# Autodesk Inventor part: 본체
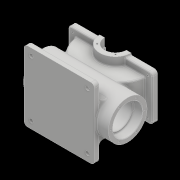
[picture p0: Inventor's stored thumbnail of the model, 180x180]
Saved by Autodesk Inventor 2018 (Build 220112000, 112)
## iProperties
Created: 2023-07
Part Number: 본체
Material: 일반
Document SubType Name: Modeling
Designer: home
Density: 1 g/cm^3
Appearance: 기본값
Author: home
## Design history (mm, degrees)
sketch "스케치1"
  geometry: L1 (-100, -100)-(100, -100); L2 (100, -100)-(100, 100); L3 (100, 100)-(-100, 100); L4 (-100, 100)-(-100, -100); L5 (-100, -100)-(100, 100); L6 (100, -100)-(-100, 100); 1 further point
  constraints: 12 end point, 2 midpoint, 2 parallel, 1 horizontal, 1 perpendicular
  dimensions: "d0" = 200 distance of L3.end L2.end; "d1" = 200 distance of L2.end L1.end
extrude "돌출1" new body sketch "스케치1" distance "d2" = 15; taper "d3" = 0 deg
sketch "스케치3"
  geometry: C1 r 55 at (60, 0); 1 further point
  constraints: 1 centre point, 1 horizontal alignment
  dimensions: "d10" = 110 diameter of C1; "d11" = 60 distance of point (0, 0) C1.centre
extrude "돌출3" join sketch "스케치3" distance "d12" = 135; taper "d14" = 0 deg; dims "d13" = 107, "d15" = 0
sketch "스케치4"
  geometry: L1 (-100, 160)-(100, 160); A1 r 100 centre (0, 160) between (-100, 160) and (100, 160); 1 further point
  constraints: 2 end point, 2 point on circle, 1 centre point, 1 horizontal, 1 vertical alignment
  dimensions: "d16" = 200 diameter of A1; "d17" = 160 distance of point (0, 0) A1.centre; "d18" = 160 distance from line of point (0, 0) L1
extrude "돌출4" join sketch "스케치4" distance "d19" = 45; taper "d21" = 0 deg; dims "d20" = 45, "d22" = 0
sketch "스케치5"
  geometry: L1 (-20, 110)-(220, 110); L2 (220, 110)-(220, -20); L3 (220, -20)-(-20, -20); L4 (-20, -20)-(-20, 110); L5 (-20, 110)-(220, -20); L6 (220, 110)-(-20, -20); 1 further point
  constraints: 12 end point, 2 midpoint, 2 parallel, 1 horizontal, 1 perpendicular
  dimensions: "d23" = 240 distance of L2.end L3.end; "d24" = 130 distance of L1.end L2.end
extrude "돌출5" join sketch "스케치5" distance "d25" = 15; taper "d26" = 0 deg
sketch "스케치7"
  geometry: L1 (-120, 160)-(120, 160) reference; L2 (-45, 160)-(45, 160); A1 r 45 centre (0, 160) between (-45, 160) and (45, 160); 1 further point
  constraints: 2 end point, 2 point on circle, 2 point on line, 1 centre point, 1 midpoint
  dimensions: "d32" = 90 diameter of A1
extrude "돌출7" join sketch "스케치7" distance "d33" = 70; taper "d35" = 0 deg; dims "d34" = 70, "d36" = 0
sketch "스케치8"
  geometry: L1 (-45, 160)-(45, 160) reference; C1 r 87 at (0, 160); 1 further point
  constraints: 1 centre point, 1 midpoint
  dimensions: "d37" = 174 diameter of C1
extrude "돌출8" cut sketch "스케치8" distance "d38" = 32; taper "d40" = 0 deg; dims "d39" = 32, "d41" = 0
hole "구멍1" diameter "d44" = 77; stored, may be unused: countersink angle "d48" = 90 deg, drill point angle "d50" = 0 deg; dims "d45" = 6, "d46" = 85, "d47" = 25, "d49" = 192, "d143" = 10, "d144" = 10
sketch "스케치9"
  geometry: 2 further points
  constraints: 1 vertical alignment
  dimensions: "d51" = 108.5 distance of point (0, -60) point (0, 48.5)
hole "구멍2" sketch "스케치9" at (0, 48.5) diameter "d52" = 4.134; stored, may be unused: countersink angle "d56" = 90 deg, drill point angle "d58" = 118 deg; dims "d53" = 10, "d54" = 85, "d55" = 25, "d57" = 12
sketch "스케치10"
  geometry: 2 further points
  dimensions: "d62" = 107 horizontal distance of point (-13, 13) point (-120, 65); "d63" = 52 vertical distance of point (-120, 65) point (-13, 13)
hole "구멍3" sketch "스케치10" at (-13, 13) diameter "d64" = 4.917; stored, may be unused: countersink angle "d68" = 90 deg, drill point angle "d70" = 118 deg; dims "d65" = 15, "d66" = 85, "d67" = 25, "d69" = 15
sketch "스케치11"
  geometry: 2 further points
  dimensions: "d77" = 80 horizontal distance of point (80, -80) point (0, 0); "d78" = 80 horizontal distance of point (0, 0) point (80, -80)
hole "구멍4" sketch "스케치11" at (80, -80) diameter "d79" = 11; stored, may be unused: countersink angle "d83" = 90 deg, drill point angle "d85" = 0 deg; dims "d80" = 12, "d81" = 28, "d82" = 2, "d84" = 15
hole "구멍5" diameter "d94" = 55; stored, may be unused: countersink angle "d98" = 90 deg, drill point angle "d100" = 0 deg; dims "d92" = 10, "d93" = 10, "d95" = 12, "d96" = 62, "d97" = 23, "d99" = 70
sketch "스케치12"
  geometry: L1 (-87, 160)-(87, 160) reference; L2 (0, 160)-(26.163, 133.837); L3 (0, 160)-(37, 160); L4 (0, 160)-(0, 150); L5 (0, 160)-(-26.163, 133.837); 3 further points
  constraints: 8 end point, 2 coincident, 2 symmetric about line, 1 equal length, 1 horizontal, 1 midpoint, 1 vertical
  dimensions: "d101" = 37 distance of L2.start L2.end; "d102" = 45 deg angle of L2 L3; "d103" = 10 distance of L2.start L4.end
hole "구멍6" sketch "스케치12" at (26.163, 133.837), (-26.163, 133.837) diameter "d104" = 4.134; stored, may be unused: countersink angle "d108" = 90 deg, drill point angle "d110" = 118 deg; dims "d105" = 10, "d106" = 62, "d107" = 23, "d109" = 12
fillet "모깎기1" dims "d111" = 15, "d112" = 10, "d113" = 10, "d114" = 1, "d115" = 1.1, "d116" = 3, "d117" = 3, "d118" = 3, "d119" = 3, "d120" = 3, "d121" = 3, "d125" = 3
sketch "스케치13"
  geometry: L1 (-90, -100)-(90, -100) reference; 2 further points
  constraints: 1 vertical alignment, 1 other
  dimensions: "d126" = 15 distance from line of L1 point (0, -85)
feature "엠보싱1" sketch "스케치13" dims "d0" = 200, "d1" = 200, "d127" = 0.5, "d128" = 0
hole "구멍7" diameter "d136" = 85; stored, may be unused: countersink angle "d140" = 90 deg, drill point angle "d142" = 0 deg; dims "d137" = 10, "d138" = 85, "d139" = 25, "d141" = 25, "d145" = 10, "d146" = 10
sketch "스케치14"
  geometry: C1 r 2.067 at (0, 48.5) reference; 2 further points
  constraints: 1 coincident
hole "구멍8" sketch "스케치14" at (0, 48.5) diameter "d147" = 4.134; stored, may be unused: countersink angle "d151" = 90 deg, drill point angle "d153" = 118 deg; dims "d148" = 10, "d149" = 4, "d150" = 25, "d152" = 12
fillet "모깎기2" dims "d157" = 1.1, "d161" = 3, "d162" = 3, "d163" = 3
chamfer "모따기2" distance "d158" = 1; stored, may be unused: second distance "d159" = 2, angle "d160" = 45 deg
node "솔리드1"
pattern_linear "직사각형 패턴1" dims "d73" = 104, "d76" = 214
pattern_linear "직사각형 패턴2" dims "d88" = 160, "d91" = 160
mirror "미러2"
pattern_circular "원형 패턴2" dims angle "d132" = 360 deg
pattern_circular "원형 패턴3" dims angle "d155" = 360 deg
